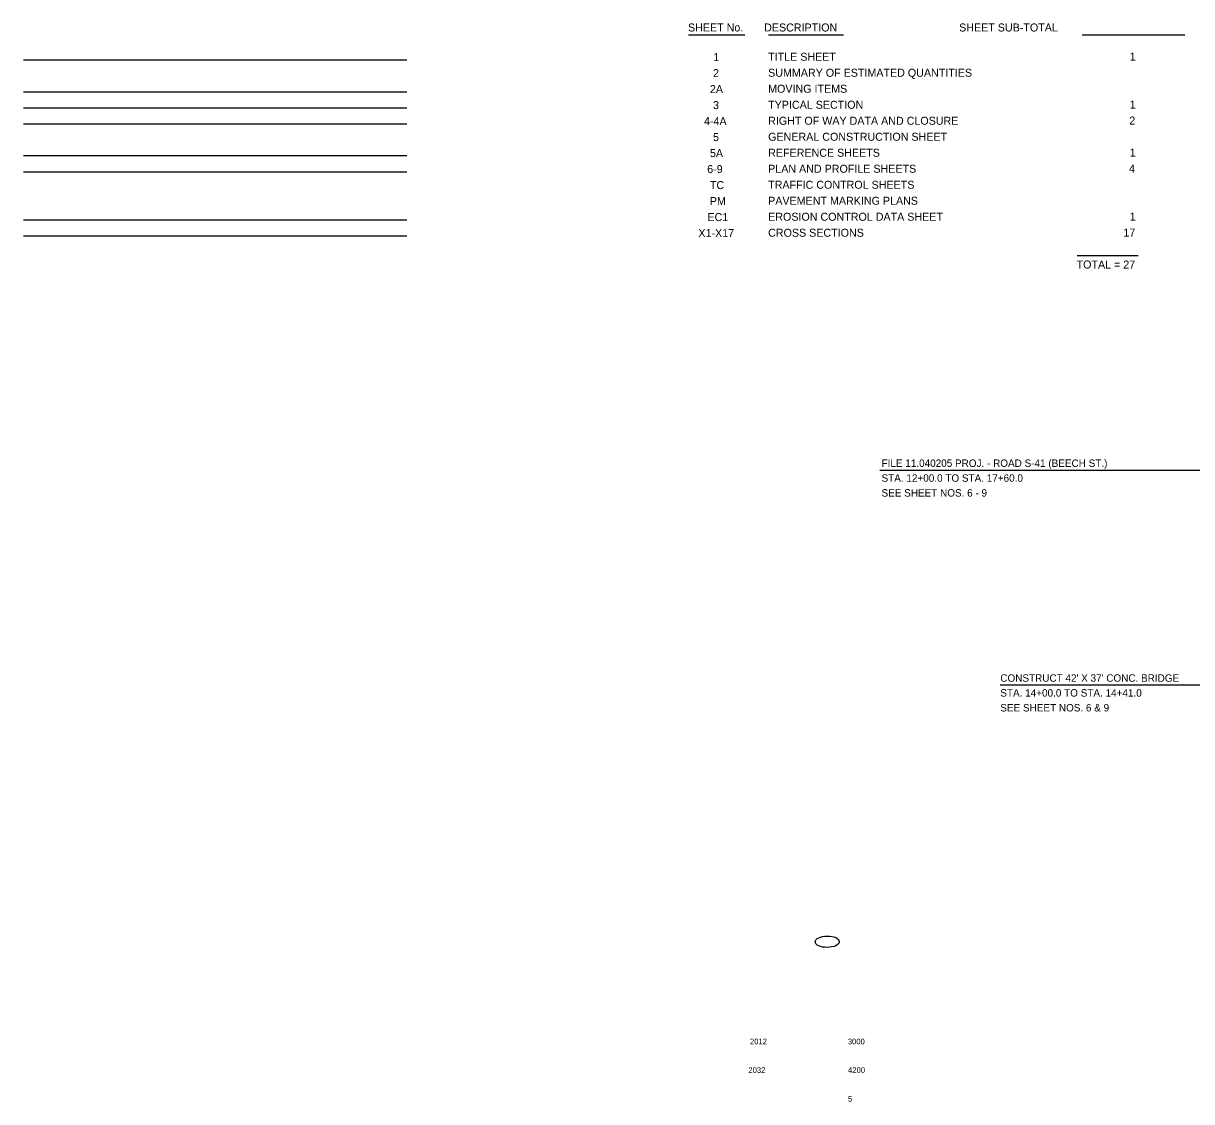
# Model space of a CAD drawing. Extents: x 160093 to 164626, y 177093 to 182727.
# Drawn here: x 160630 to 161652, y 177112 to 178055 of the extents above; entities that cross this region are included whole.
import ezdxf

# ---------------------------------------------------------------- set-up
doc = ezdxf.new("R2010")
doc.units = 0
for name, color, linetype in [('Default', 7, 'Continuous'), ('Level 39', 7, 'Continuous'), ('RD_SHT_TX', 7, 'Continuous')]:
    doc.layers.add(name, color=color, linetype=linetype)

msp = doc.modelspace()

# ---------------------------------------------------------------- linework, layer by layer
at = {"layer": 'Default'}
for p, q in [((161212.1, 178045), (161261.3, 178045)), ((161282, 178045), (161347.8, 178045)), ((161556.4, 178045), (161646.4, 178045)), ((161552.2, 177852), (161605.5, 177852))]:
    msp.add_line(p, q, dxfattribs=at)
msp.add_ellipse((161333.5, 177251.5), major_axis=(10.5, 0.1), ratio=0.473554, dxfattribs=at)
at = {"layer": 'Level 39'}
for p, q in [((161379.4, 177664.1), (161379.4, 177664.1)), ((161379.4, 177664.1), (161665.7, 177664.1)), ((161484.7, 177476.3), (161484.7, 177476.3)), ((161484.7, 177476.3), (161668.4, 177476.3))]:
    msp.add_line(p, q, dxfattribs=at)
at = {"layer": 'RD_SHT_TX'}
for p, q in [((160630.4, 178023.2), (160965.8, 178023.2)), ((160630.4, 177995.2), (160965.8, 177995.2)), ((160630.4, 177981.2), (160965.8, 177981.2)), ((160630.4, 177967.2), (160965.8, 177967.2)), ((160630.4, 177939.4), (160965.8, 177939.4)), ((160630.4, 177925.1), (160965.8, 177925.1)), ((160630.4, 177883.2), (160965.8, 177883.2)), ((160630.4, 177869.2), (160965.8, 177869.2))]:
    msp.add_line(p, q, dxfattribs=at)

# ---------------------------------------------------------------- texts
at = {"layer": 'Default'}
for s, height, p in [('SHEET No.       DESCRIPTION                                         SHEET SUB-TOTAL', 7, (161211.7, 178048)), ('1', 7, (161233.8, 178022.1)), ('TITLE SHEET', 7, (161281.8, 178022.4)), ('1', 7, (161598.1, 178022.6)), ('2', 7, (161233.6, 178008.1)), ('SUMMARY OF ESTIMATED QUANTITIES', 7, (161281.8, 178008.4)), ('2A', 7, (161230.9, 177994.1)), ('MOVING ITEMS', 7, (161281.8, 177994.4)), ('3 ', 7, (161233.6, 177980.1)), ('TYPICAL SECTION', 7, (161281.8, 177980.4)), ('1', 7, (161598.1, 177980.6)), ('4-4A', 7, (161225.7, 177966.1)), ('RIGHT OF WAY DATA AND CLOSURE', 7, (161281.8, 177966.4)), ('2', 7, (161597.7, 177966.6)), ('5', 7, (161233.6, 177952.1)), ('GENERAL CONSTRUCTION SHEET', 7, (161281.8, 177952.4)), ('5A', 7, (161230.9, 177938.1)), ('REFERENCE SHEETS', 7, (161281.8, 177938.4)), ('1', 7, (161598.1, 177938.6)), ('6-9', 7, (161228.5, 177924.1)), ('PLAN AND PROFILE SHEETS', 7, (161281.8, 177924.4)), ('4', 7, (161597.5, 177924.6)), ('TRAFFIC CONTROL SHEETS', 7, (161281.8, 177910.4)), ('TC', 7, (161230.9, 177910.1)), ('PM', 7, (161230.8, 177896.1)), ('PAVEMENT MARKING PLANS', 7, (161281.8, 177896.4)), ('EC1', 7, (161228.7, 177882.1)), ('EROSION CONTROL DATA SHEET', 7, (161281.8, 177882.4)), ('1', 7, (161598.1, 177882.6)), ('X1-X17', 7, (161220.8, 177868.1)), ('CROSS SECTIONS', 7, (161281.8, 177868.4)), ('17', 7, (161592.6, 177868.6)), ('TOTAL = 27', 7, (161551.6, 177840.6)), ('FILE 11.040205 PROJ. - ROAD S-41 (BEECH ST.) ', 6.5, (161381, 177667)), ('STA. 12+00.0 TO STA. 17+60.0', 6.5, (161381, 177654)), ('SEE SHEET NOS. 6 - 9', 6.5, (161381, 177641)), ("CONSTRUCT 42' X 37' CONC. BRIDGE", 6.5, (161484.9, 177479)), ('STA. 14+00.0 TO STA. 14+41.0', 6.5, (161484.9, 177466)), ('SEE SHEET NOS. 6 & 9', 6.5, (161484.9, 177453)), ('2012', 5, (161265.9, 177161.7)), ('3000', 5, (161351.5, 177161.7)), ('2032', 5, (161264.5, 177136.7)), ('4200', 5, (161351.7, 177136.7)), ('5', 5, (161351.6, 177111.6))]:
    msp.add_text(s, height=height, dxfattribs=at).set_placement(p)

doc.saveas('drawing.dxf')
